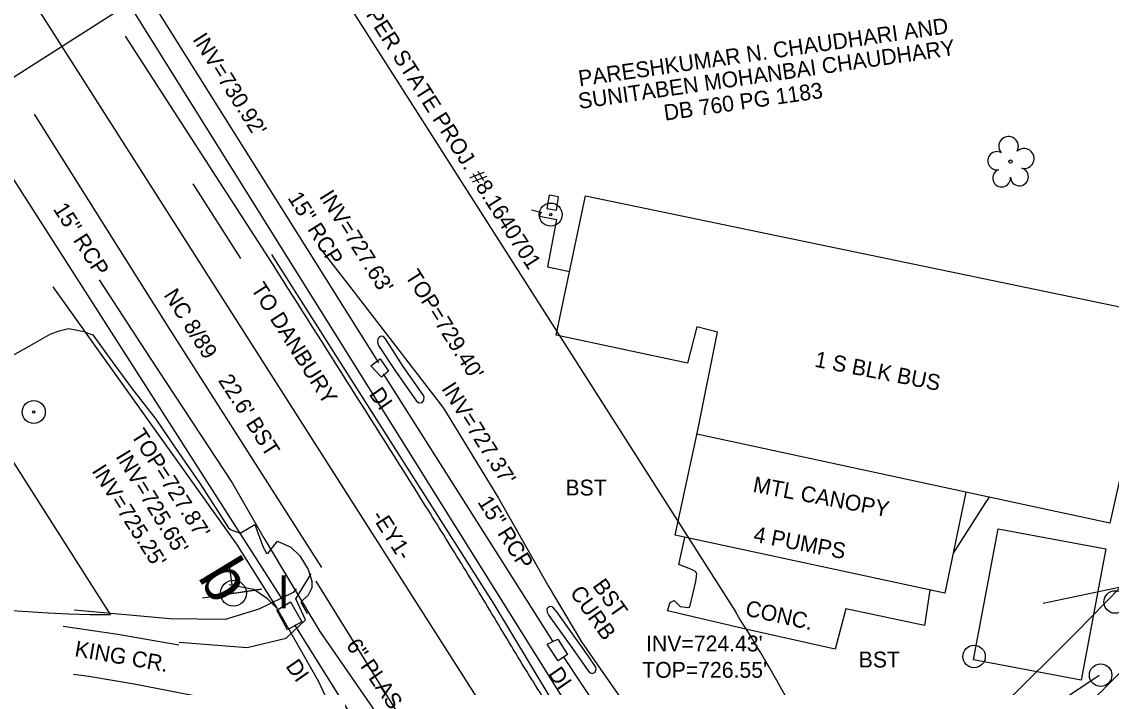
# Model space of a CAD drawing. Extents: x 1645945 to 2447332, y 713118 to 970361.
# Drawn here: x 1646155.6 to 1646361.8, y 969589.2 to 969715.1 of the extents above; entities that cross this region are included whole.
import ezdxf

# ---------------------------------------------------------------- set-up
doc = ezdxf.new("R2010")
doc.units = 0
for name, color, linetype in [('Exist Building', 7, 'Continuous'), ('Exist Building Text', 7, 'Continuous'), ('Exist Horizontal Alignment', 7, 'Continuous'), ('Exist Horizontal Alignment Direction Label', 7, 'Continuous'), ('Exist Other Culture Area Outline', 7, 'Continuous'), ('Exist Other Culture Area Outline Leader', 7, 'Continuous'), ('Exist Other Culture Located Object CELL', 7, 'Continuous'), ('Exist Other Culture Well CELL', 7, 'Continuous'), ('Exist Other Culture Well Leader', 7, 'Continuous'), ('Exist Property Deed Book Text', 7, 'Continuous'), ('Exist Property Owner Text', 7, 'Continuous'), ('Exist Right of Way Line', 7, 'Continuous'), ('Exist Right of Way Line Text', 7, 'Continuous'), ('Exist Right of Way Width CELL', 7, 'Continuous'), ('Exist Roads Curbs', 7, 'Continuous'), ('Exist Roads Curbs Text', 7, 'Continuous'), ('Exist Roads EOP', 7, 'Continuous'), ('Exist Roads EOP Other', 7, 'Continuous'), ('Exist Roads EOP Other Text', 7, 'Continuous'), ('Exist Roads EOP Text', 7, 'Continuous'), ('Exist Roads EOT', 7, 'Continuous'), ('Exist Roads EOT Leader', 7, 'Continuous'), ('Exist Roads EOT Text', 7, 'Continuous'), ('Exist Structure Minor Drop Inlet', 7, 'Continuous'), ('Exist Structure Minor Drop Inlet Text', 7, 'Continuous'), ('Exist Structure Minor Drop Inlet Top Elevation', 7, 'Continuous'), ('Exist Structure Minor Pipes RCP 15 Inch', 7, 'Continuous'), ('Exist Structure Minor Pipes RCP 15 Inch Invert', 7, 'Continuous'), ('Exist Structure Minor Pipes RCP 15 Inch Text', 7, 'Continuous'), ('Exist Structure Minor Pipes RCP 18 Inch', 7, 'Continuous'), ('Exist Structure Minor Pipes RCP 18 Inch Invert', 7, 'Continuous'), ('Exist Utilities Power Joint Use Telephone CELL', 7, 'Continuous'), ('Exist Utilities Sanitary Sewer UG Line', 7, 'Continuous'), ('Exist Utilities Telephone Pedestal CELL', 7, 'Continuous'), ('Exist Utilities Telephone UG Conduit SUE LOS B', 7, 'Continuous'), ('Exist Utilities Telephone UG FO SUE LOS C', 7, 'Continuous'), ('Exist Utilities Water UG Line SUE LOS B', 7, 'Continuous'), ('Exist Utilities Water UG Line SUE LOS B Text', 7, 'Continuous'), ('Exist Utilities Water Valve CELL', 7, 'Continuous'), ('Exist Vegetation Tree CELL', 7, 'Continuous')]:
    doc.layers.add(name, color=color, linetype=linetype)

msp = doc.modelspace()

# ---------------------------------------------------------------- linework, layer by layer
at = {"layer": 'Exist Building'}
for p, q in [((1646252.04, 969679.53), (1646254.01, 969679.02)), ((1646334.26, 969626.09), (1646283.36, 969637.05))]:
    msp.add_line(p, q, dxfattribs=at)
msp.add_lwpolyline([(1646262.27, 969682.17), (1646370.37, 969659.74), (1646361.5, 969620.22), (1646334.26, 969626.09), (1646330.25, 969606.95), (1646279.24, 969617.92), (1646283.52, 969637.8), (1646287.23, 969656.4), (1646283.31, 969657.36), (1646281.56, 969650.49), (1646256.7, 969655.82)], close=True, dxfattribs=at)
at = {"layer": 'Exist Horizontal Alignment'}
msp.add_line((1646158.92, 969717.09), (1646248.52, 969576.48), dxfattribs=at)
at = {"layer": 'Exist Other Culture Area Outline'}
msp.add_lwpolyline([(1646340.35, 969619.16), (1646360.74, 969615.33), (1646356.07, 969590.49), (1646335.68, 969594.33)], close=True, dxfattribs=at)
at = {"layer": 'Exist Other Culture Area Outline Leader'}
msp.add_lwpolyline([(1646348.88, 969605.08), (1646366.88, 969608.89), (1646371.81, 969614)], dxfattribs=at)
at = {"layer": 'Exist Other Culture Located Object CELL'}
msp.add_lwpolyline([(1646256.75, 969679.48), (1646257.18, 969681.99), (1646255.36, 969682.3), (1646254.93, 969679.8)], close=True, dxfattribs=at)
for centre, radius in [((1646255.67, 969678.63), 2.18), ((1646255.67, 969678.63), 0.24), ((1646157.83, 969641.26), 2.18), ((1646157.83, 969641.26), 0.24)]:
    msp.add_circle(centre, radius, dxfattribs=at)
at = {"layer": 'Exist Other Culture Well CELL'}
for centre in [(1646362.49, 969605.3), (1646335.8, 969594.98), (1646359.76, 969591.44)]:
    msp.add_circle(centre, 2.13, dxfattribs=at)
at = {"layer": 'Exist Other Culture Well Leader'}
msp.add_lwpolyline([(1646359.5, 969591.41), (1646346.18, 969582.49), (1646341.32, 969587.35)], dxfattribs=at)
at = {"layer": 'Exist Right of Way Line'}
for p, q in [((1646201.09, 969743.96), (1646290.69, 969603.35)), ((1646172.39, 969602.91), (1646100.95, 969715.03)), ((1646404.52, 969649.96), (1646355.06, 969599.48))]:
    msp.add_line(p, q, dxfattribs=at)
for centre, radius, start, end in [((1646173.54, 969858.75), 255.84, 214.1779, 269.7419), ((1646037.69, 969442.13), 300, 23.3127, 32.506), ((1645951.5, 969994.91), 565, 309.8047, 315.5831)]:
    msp.add_arc(centre, radius, start, end, dxfattribs=at)
at = {"layer": 'Exist Right of Way Width CELL'}
msp.add_line((1646120.95, 969683.63), (1646187.89, 969726.29), dxfattribs=at)
at = {"layer": 'Exist Roads Curbs'}
for points in [[(1646231.46, 969644.58), (1646227.75, 969649.89), (1646224.42, 969655.14), (1646224.04, 969655.55), (1646223.67, 969655.64), (1646223.46, 969655.56), (1646223.23, 969655.39), (1646222.97, 969655.09), (1646222.91, 969654.53), (1646223.1, 969653.86), (1646226.18, 969649.17), (1646230.25, 969643.32), (1646230.8, 969643), (1646231.34, 969643.04), (1646231.68, 969643.5), (1646231.72, 969644.12)], [(1646264.21, 969592.93), (1646262.77, 969595.12), (1646256.86, 969603.45), (1646256.05, 969604.34), (1646255.49, 969604.45), (1646255.14, 969604.22), (1646254.93, 969604), (1646255.03, 969603.36), (1646255.31, 969602.72), (1646259.49, 969596.93), (1646262.74, 969592.24), (1646263.22, 969591.88), (1646263.53, 969591.75), (1646264.07, 969592.04), (1646264.3, 969592.57)]]:
    msp.add_lwpolyline(points, close=True, dxfattribs=at)
at = {"layer": 'Exist Roads EOP'}
msp.add_line((1646202.27, 969670.52), (1646175.18, 969712.41), dxfattribs=at)
for points in [[(1646169.02, 969655.88), (1646169.03, 969655.84), (1646172.08, 969651.56), (1646176.43, 969645.64), (1646180.91, 969639.89), (1646184.66, 969634.41), (1646189.19, 969627.85), (1646194.72, 969619.32), (1646195.21, 969618.96), (1646196.88, 969618.31), (1646199.67, 969619.94), (1646201.25, 969615.66), (1646201.87, 969614.55), (1646202.21, 969614.55), (1646203.95, 969616.84), (1646206.48, 969615.65), (1646208.17, 969614.01), (1646209.76, 969611.43), (1646210.49, 969609.27), (1646210.46, 969607.99), (1646209.78, 969606.57), (1646208.4, 969605.28), (1646209.58, 969603.09)], [(1646185.35, 969597.69), (1646198.25, 969596.69), (1646205.62, 969598.44), (1646209.27, 969601.94), (1646207.42, 969605.88), (1646210.37, 969610.63)]]:
    msp.add_lwpolyline(points, dxfattribs=at)
for points in [[(1646260.63, 969575.85), (1646258.14, 969580.63), (1646251.55, 969591.51), (1646244.97, 969602.4), (1646238.35, 969613.26), (1646231.63, 969624.06), (1646202.27, 969670.52)], [(1646384.59, 969614.07), (1646363.63, 969592.14), (1646351.92, 969580.65), (1646345.86, 969575.11), (1646339.73, 969569.64), (1646334.58, 969565.16), (1646329.36, 969560.75), (1646318.86, 969552), (1646315.45, 969549.18), (1646312.01, 969546.44), (1646308.49, 969543.75), (1646304.83, 969541.11), (1646302.42, 969539.76), (1646299.77, 969538.9), (1646294.52, 969539.25), (1646282.77, 969544.37), (1646279.95, 969545.5), (1646277.2, 969546.85), (1646276.76, 969547.14)], [(1646373.7, 969456.15), (1646346.78, 969454.01), (1646328.12, 969455.82), (1646313.73, 969464.34), (1646305.52, 969476.97), (1646302.12, 969486.35), (1646303.66, 969500.55), (1646311.37, 969513.37), (1646318.37, 969523.3), (1646325.82, 969532.44), (1646336.85, 969542.47), (1646347.88, 969552.31), (1646363.63, 969567.2), (1646396.16, 969600.3)]]:
    msp.add_spline(points, degree=3, dxfattribs=at)
at = {"layer": 'Exist Roads EOP Other'}
for points in [[(1646253.75, 969679.15), (1646253.56, 969678.31), (1646256.76, 969677.68), (1646255.07, 969668.74), (1646257.79, 969668.18), (1646259.25, 969667.89)], [(1646152.57, 969651.18), (1646153.81, 969651.97), (1646157.86, 969654.2), (1646160.95, 969655.97), (1646162.66, 969656.61), (1646164.42, 969657.04), (1646166.08, 969656.78), (1646167.29, 969656.5), (1646168.24, 969656.13), (1646169.02, 969655.88)], [(1646338.65, 969625.15), (1646337.85, 969623.97), (1646331.84, 969614.56)], [(1646327.44, 969607.55), (1646326.42, 969600.85), (1646311.51, 969603.99), (1646309.5, 969596.36), (1646292.89, 969600.09), (1646277.79, 969603.65), (1646278.26, 969605.21), (1646279.04, 969605.6), (1646280.18, 969604.45), (1646281.77, 969604.28), (1646282.03, 969604.4), (1646283.16, 969609.17), (1646283.32, 969610.61), (1646283.08, 969611.09), (1646282.22, 969611.52), (1646279.92, 969612.4), (1646281.07, 969617.53)], [(1646163.41, 969600.7), (1646173.77, 969599.2), (1646185.27, 969597.22)], [(1646165.35, 969591.66), (1646168.28, 969591.28), (1646176.87, 969589.79), (1646186.22, 969588), (1646189.89, 969587.28), (1646190.4, 969587.01), (1646190.9, 969586.01), (1646191.32, 969585.06)]]:
    msp.add_lwpolyline(points, dxfattribs=at)
at = {"layer": 'Exist Roads EOT'}
msp.add_line((1646211.25, 969609.25), (1646236.61, 969568.35), dxfattribs=at)
msp.add_lwpolyline([(1646212.35, 969611.82), (1646183.49, 969657.11), (1646157.99, 969697.67)], dxfattribs=at)
at = {"layer": 'Exist Roads EOT Leader'}
msp.add_line((1646187.92, 969684.43), (1646196.98, 969670.3), dxfattribs=at)
at = {"layer": 'Exist Structure Minor Drop Inlet'}
for points in [[(1646223.37, 969651.33), (1646225, 969648.98), (1646223.66, 969647.83), (1646221.65, 969650.02), (1646223.37, 969651.33)], [(1646203.83, 969603.72), (1646206.45, 969605.34), (1646208.58, 969601.55), (1646205.86, 969600), (1646203.83, 969603.72)], [(1646255.03, 969597.29), (1646257.01, 969598.23), (1646258.86, 969595.35), (1646257.06, 969594.19), (1646255.03, 969597.29)]]:
    msp.add_lwpolyline(points, dxfattribs=at)
at = {"layer": 'Exist Structure Minor Pipes RCP 15 Inch'}
for p, q in [((1646128.97, 969724.35), (1646205.55, 969604.69)), ((1646181.59, 969716.71), (1646223.1, 969650.57)), ((1646223.98, 969648.49), (1646256.03, 969597.89)), ((1646258.04, 969594.97), (1646288.86, 969548.56))]:
    msp.add_line(p, q, dxfattribs=at)
at = {"layer": 'Exist Structure Minor Pipes RCP 18 Inch'}
msp.add_line((1646207.18, 969600.97), (1646241.88, 969545.45), dxfattribs=at)
at = {"layer": 'Exist Utilities Power Joint Use Telephone CELL'}
msp.add_line((1646195.63, 969606.95), (1646195.63, 969606.95), dxfattribs=at)
msp.add_lwpolyline([(1646189.75, 969606.07), (1646200.97, 969607.72), (1646195.63, 969606.93), (1646194.79, 969612.52)], dxfattribs=at)
msp.add_circle((1646195.63, 969606.96), 2.45, dxfattribs=at)
at = {"layer": 'Exist Utilities Sanitary Sewer UG Line'}
msp.add_line((1646096.45, 969845.65), (1646327.92, 969475.04), dxfattribs=at)
at = {"layer": 'Exist Utilities Telephone UG Conduit SUE LOS B'}
msp.add_lwpolyline([(1646211.87, 969672.44), (1646218.06, 969664.51), (1646227.56, 969652.15), (1646235.4, 969641.97), (1646245.81, 969624.96), (1646255.19, 969608.38), (1646261.48, 969597.75), (1646270.44, 969584.88)], dxfattribs=at)
at = {"layer": 'Exist Utilities Telephone UG FO SUE LOS C'}
for points in [[(1646202.85, 969671.1), (1646244.91, 969604.9), (1646262.03, 969576.49), (1646314.81, 969484.38), (1646321.44, 969466.08), (1646326, 969459.52), (1646329.74, 969456.67), (1646331.74, 969455.12)], [(1646161.43, 969664.95), (1646196.19, 969616.22), (1646203.85, 969604.15)], [(1646194.8, 969608.59), (1646199.47, 969607.75), (1646201.91, 969606.06), (1646203.85, 969604.15)], [(1646203.85, 969604.15), (1646211.74, 969590.22), (1646241.23, 969526.88), (1646267.12, 969471.85), (1646269.09, 969465.94)]]:
    msp.add_lwpolyline(points, dxfattribs=at)
at = {"layer": 'Exist Utilities Water UG Line SUE LOS B'}
for points in [[(1646170.24, 969666.26), (1646179.89, 969651.43), (1646195.41, 969627.85), (1646201.47, 969617.31), (1646211.97, 969599.71), (1646220.72, 969587.04), (1646228.76, 969575.31), (1646233.7, 969567.15), (1646240.29, 969555.33), (1646247.6, 969540.83), (1646253.09, 969528.92), (1646261.6, 969502.98), (1646265.06, 969491.29)], [(1646207.48, 969607.76), (1646206.95, 969607.1), (1646200.45, 969603.91), (1646194.04, 969601.97), (1646183.58, 969602.12), (1646165.51, 969603.75)]]:
    msp.add_lwpolyline(points, dxfattribs=at)
at = {"layer": 'Exist Vegetation Tree CELL'}
msp.add_line((1646342.72, 969688.67), (1646342.72, 969688.67), dxfattribs=at)
msp.add_circle((1646342.72, 969688.67), 0.326, dxfattribs=at)
for centre, radius, start, end in [((1646342.34, 969691.54), 1.86, 330.1651, 219.7134), ((1646340.12, 969688.82), 1.73, 62.6636, 279.3457), ((1646345.27, 969689.25), 1.9, 257.1011, 134.1999), ((1646341.02, 969685.55), 1.69, 111.5671, 6.231), ((1646344.4, 969685.77), 1.7, 181.2822, 74.56)]:
    msp.add_arc(centre, radius, start, end, dxfattribs=at)

# ---------------------------------------------------------------- texts
at = {"layer": 'Exist Building Text'}
for s, rotation, p in [('1 S BLK BUS', 348.9584, (1646305.48, 969649.86)), ('MTL CANOPY', 349.3744, (1646293.8, 969626.16)), ('4 PUMPS', 349.1465, (1646293.9, 969616.72))]:
    msp.add_text(s, height=3, rotation=rotation, dxfattribs=at).set_placement(p)
at = {"layer": 'Exist Horizontal Alignment Direction Label'}
msp.add_text('-EY1-', height=3, rotation=302.506, dxfattribs=at).set_placement((1646221.65, 969621.57))
at = {"layer": 'Exist Property Deed Book Text'}
msp.add_text('DB 760 PG 1183', height=3, rotation=8.183, dxfattribs=at).set_placement((1646277.31, 969696.41))
at = {"layer": 'Exist Property Owner Text'}
for s, p in [('PARESHKUMAR N. CHAUDHARI AND ', (1646261.13, 969702.9)), ('SUNITABEN MOHANBAI CHAUDHARY', (1646261.1, 969698.61))]:
    msp.add_text(s, height=3, rotation=8.183, dxfattribs=at).set_placement(p)
at = {"layer": 'Exist Right of Way Line Text'}
msp.add_text('EXISTING R/W PER STATE PROJ. #8.1640701', height=3, rotation=302.506, dxfattribs=at).set_placement((1646205.15, 969740.75))
at = {"layer": 'Exist Roads Curbs Text'}
for s, p in [('CURB', (1646259.19, 969607.05)), ('BST', (1646263.47, 969608.37))]:
    msp.add_text(s, height=3, rotation=305.4018, dxfattribs=at).set_placement(p)
at = {"layer": 'Exist Roads EOP Other Text'}
for s, rotation, p in [('CONC.', 347.3434, (1646292.34, 969602.77)), ('KING CR.', 350.2229, (1646165.44, 969595.06))]:
    msp.add_text(s, height=3, rotation=rotation, dxfattribs=at).set_placement(p)
at = {"layer": 'Exist Roads EOP Text'}
for p in [(1646258.47, 969625.46), (1646313.97, 969592.91)]:
    msp.add_text('BST', height=3, rotation=359.9014, dxfattribs=at).set_placement(p)
at = {"layer": 'Exist Roads EOT Text'}
for s, rotation, p in [('TO DANBURY', 302.4202, (1646198.83, 969664.59)), ("NC 8/89    22.6' BST", 302.551, (1646182.33, 969663.4))]:
    msp.add_text(s, height=3, rotation=rotation, dxfattribs=at).set_placement(p)
at = {"layer": 'Exist Structure Minor Drop Inlet Text'}
for p in [(1646221.18, 969644.63), (1646205.4, 969593.15), (1646255.09, 969591.71)]:
    msp.add_text('DI', height=3, rotation=304.6263, dxfattribs=at).set_placement(p)
at = {"layer": 'Exist Structure Minor Drop Inlet Top Elevation'}
for s, rotation, p in [("TOP=729.40'", 302.2863, (1646228.02, 969667.03)), ("TOP=727.87'", 302.6664, (1646176.14, 969636.88))]:
    msp.add_text(s, height=3, rotation=rotation, dxfattribs=at).set_placement(p)
msp.add_text("TOP=726.55'", height=3, dxfattribs=at).set_placement((1646273, 969590.95))
at = {"layer": 'Exist Structure Minor Pipes RCP 15 Inch Invert'}
for s, rotation, p in [("INV=730.92'", 302.2615, (1646187.79, 969711.82)), ("INV=727.63'", 302.2802, (1646211.77, 969682.07)), ("INV=727.37'", 302.457, (1646234.89, 969645.69)), ("INV=725.65'", 301.3952, (1646173.24, 969632.87))]:
    msp.add_text(s, height=3, rotation=rotation, dxfattribs=at).set_placement(p)
msp.add_text("INV=724.43'", height=3, dxfattribs=at).set_placement((1646273.73, 969595.94))
at = {"layer": 'Exist Structure Minor Pipes RCP 15 Inch Text'}
for rotation, p in [(302.1175, (1646205.81, 969681.81)), (302.6192, (1646161.41, 969679.69)), (302.3483, (1646241.74, 969624.23))]:
    msp.add_text('15" RCP', height=3, rotation=rotation, dxfattribs=at).set_placement(p)
at = {"layer": 'Exist Structure Minor Pipes RCP 18 Inch Invert'}
msp.add_text("INV=725.25'", height=3, rotation=302.6051, dxfattribs=at).set_placement((1646168.71, 969630.11))
at = {"layer": 'Exist Utilities Telephone Pedestal CELL'}
msp.add_text('b', height=8.81, rotation=301.2971, dxfattribs=at).set_placement((1646188.75, 969610.07))
at = {"layer": 'Exist Utilities Water UG Line SUE LOS B Text'}
msp.add_text('6" PLAS', height=3, rotation=304.6277, dxfattribs=at).set_placement((1646216.83, 969597.07))
at = {"layer": 'Exist Utilities Water Valve CELL'}
msp.add_text('I', height=6.25, dxfattribs=at).set_placement((1646203.98, 969604.1))

doc.saveas('drawing.dxf')
